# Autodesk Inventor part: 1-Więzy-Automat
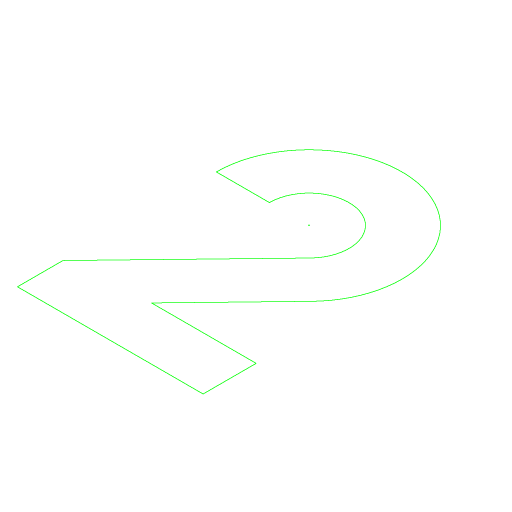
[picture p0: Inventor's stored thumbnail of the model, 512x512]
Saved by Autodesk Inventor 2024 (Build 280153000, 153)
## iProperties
Company: ATC
Shininess: 21.0
Length Units: 11269
Angle Units: 11279
Time Units: 11290
Mass Units: 11283
Length Display Precision: 3
Angle Display Precision: 2
Compacted: True
Created: 2023-03
Part Number: 1-Więzy-Automat
Document SubType Name: Modeling
Designer: Andrzej Jaskulski
Material: Kurs-AJ
Density: 1 g/cm^3
Appearance: Kurs-AJ
Checked By: A.J.
Engr Approved By: Andrzej Jaskulski
Mfg Approved By: Andrzej Jaskulski
Authority: A.J.
Density: 0.0
Volumn: 0.0
Area: 0.0
PropertySet Name: Model Information
Control State: 0
Master: False
Checked Out: False
Title: A.J.: Kurs R2024-MEP
Author: Andrzej Jaskulski
Revision Number: 1/24
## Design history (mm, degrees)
sketch "Szkic wzorcowy"
  geometry: L1 (140, 0.063)-(0, 0.063) reference; L2 (0, 0.063)-(0, 34.389) reference; L3 (0, 150.063)-(40, 150.063); L4 (140, 0.063)-(140, 40.063); L5 (140, 40.063)-(61.086, 40.063); L6 (61.086, 40.063)-(120.354, 101.437); L7 (91.58, 129.223)-(0, 34.389); A1 r 30 centre (70, 150.063) between (91.58, 129.223) and (40, 150.063); A2 r 70 centre (70, 150.063) between (120.354, 101.437) and (0, 150.063)
  constraints: 14 end point, 4 perpendicular, 4 point on circle, 3 tangent, 2 centre point, 2 parallel, 1 coincident, 1 other
  dimensions: "d0" = 140 distance of L1.start L1.end; "d1" = 150 vertical distance of A1.centre L1.end; "d2" = 70 horizontal distance of L1.end A1.centre; "d3" = 46 deg angle of L6 L5; "d5" = 30 radius of A1; "d6" = 70 radius of A2; "d18" = 40 distance between parallel lines of L5 L1
sketch "Do nakładania więzów"
  geometry: L1 (140, 0.063)-(0, 0.063) reference; L2 (0, 0.063)-(0, 34.389) reference; L3 (0, 150.063)-(40, 150.063); L4 (140, 40.063)-(61.086, 40.063); L5 (61.086, 40.063)-(120.354, 101.437); L6 (91.58, 129.223)-(0, 34.389); L7 (140, 0.063)-(140, 40.063); A1 r 70 centre (70, 150.063) between (120.354, 101.437) and (0, 150.063); A2 r 30 centre (70, 150.063) between (91.58, 129.223) and (40, 150.063)
  constraints: 14 end point, 4 point on circle, 2 centre point, 1 coincident
node "Korpusy bryłowe"
node "Korpusy powierzchniowe"
other parameters: "d9" = 90 deg
